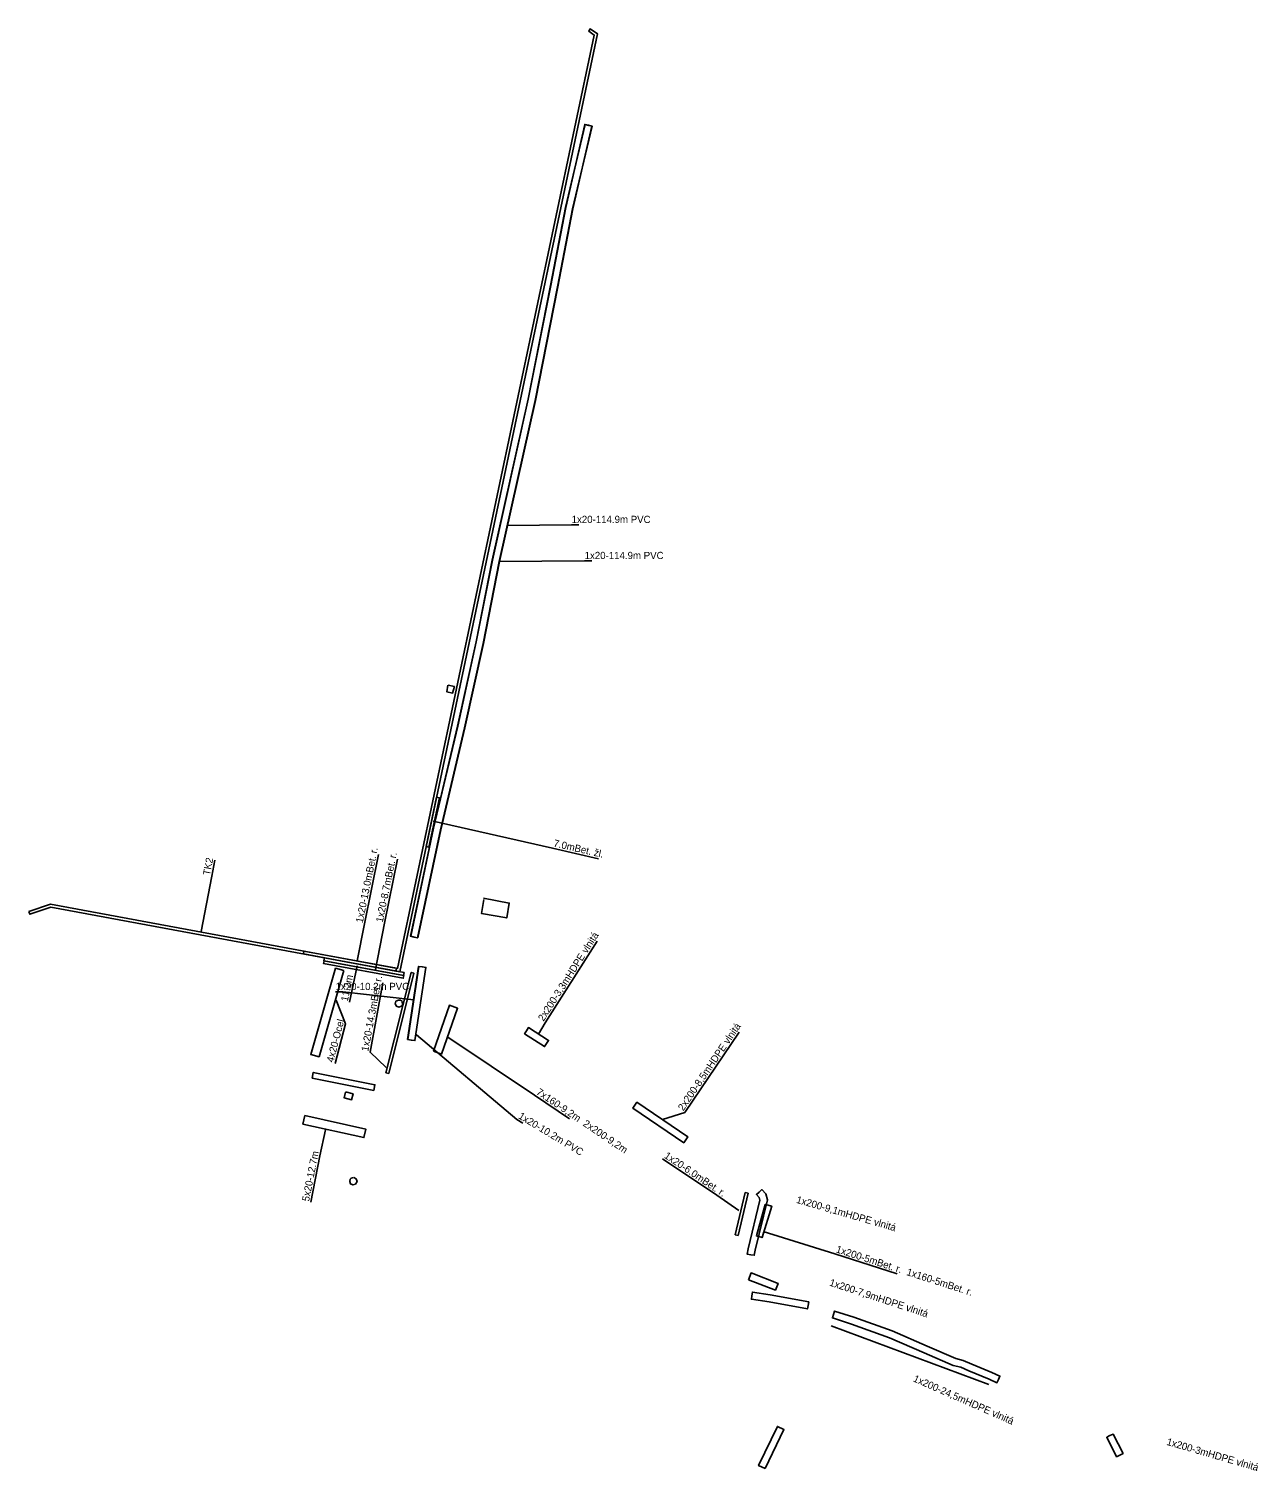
# Model space of a CAD drawing. Extents: x -739775 to -739098, y -1046233 to -1045777.
# Drawn here: x -739775.1 to -739605, y -1045977 to -1045777.5 of the extents above; entities that cross this region are included whole.
import ezdxf

# ---------------------------------------------------------------- set-up
doc = ezdxf.new("R2010")
doc.units = 0
for name, color, linetype in [('Chránička', 7, 'Continuous'), ('ST_CHRANICKA_POPIS', 7, 'Continuous'), ('ST_OBECNA_STAVBA', 7, 'Continuous')]:
    doc.layers.add(name, color=color, linetype=linetype)

msp = doc.modelspace()

# ---------------------------------------------------------------- linework, layer by layer
at = {"layer": 'Chránička'}
for points in [[(-739775.059, -1045899.583), (-739772.063, -1045898.585), (-739724.041, -1045907.446), (-739696.828, -1045778.31), (-739697.577, -1045777.78), (-739697.393, -1045777.45), (-739696.384, -1045778.138), (-739723.729, -1045907.91), (-739772.035, -1045898.997), (-739774.933, -1045899.962), (-739775.059, -1045899.583)], [(-739721.75, -1045903.11), (-739722.239, -1045903.007), (-739719.078, -1045888.051), (-739715.747, -1045873.949), (-739713.18, -1045862.278), (-739710.949, -1045850.957), (-739705.979, -1045828.687), (-739702.871, -1045812.944), (-739700.789, -1045802.165), (-739698.066, -1045790.695), (-739697.58, -1045790.81), (-739697.094, -1045790.925), (-739699.811, -1045802.375), (-739701.889, -1045813.136), (-739705.001, -1045828.893), (-739709.971, -1045851.163), (-739712.2, -1045862.482), (-739714.773, -1045874.171), (-739718.102, -1045888.269), (-739721.261, -1045903.213), (-739721.75, -1045903.11)], [(-739721.73, -1045903.11), (-739722.219, -1045903.006), (-739719.048, -1045888.051), (-739715.717, -1045873.949), (-739713.139, -1045862.278), (-739710.909, -1045850.957), (-739705.949, -1045828.687), (-739702.831, -1045812.944), (-739700.749, -1045802.167), (-739698.127, -1045790.679), (-739697.64, -1045790.79), (-739697.153, -1045790.901), (-739699.771, -1045802.373), (-739701.849, -1045813.136), (-739704.971, -1045828.893), (-739709.931, -1045851.163), (-739712.161, -1045862.482), (-739714.743, -1045874.171), (-739718.072, -1045888.269), (-739721.241, -1045903.214), (-739721.73, -1045903.11)], [(-739719.692, -1045890.686), (-739720.084, -1045890.604), (-739718.642, -1045883.754), (-739718.251, -1045883.836), (-739719.692, -1045890.686)], [(-739724.202, -1045907.416), (-739724.274, -1045907.81), (-739737.059, -1045905.451), (-739736.986, -1045905.058), (-739724.202, -1045907.416)], [(-739731.461, -1045907.757), (-739734.888, -1045919.671), (-739736.041, -1045919.34), (-739732.614, -1045907.426), (-739731.461, -1045907.757)], [(-739723.187, -1045908.415), (-739723.259, -1045908.809), (-739734.273, -1045906.777), (-739734.201, -1045906.384), (-739723.187, -1045908.415)], [(-739723.139, -1045908.019), (-739723.211, -1045908.413), (-739734.225, -1045906.38), (-739734.153, -1045905.987), (-739723.139, -1045908.019)], [(-739722.16, -1045917.36), (-739722.654, -1045917.285), (-739721.124, -1045907.165), (-739720.63, -1045907.24), (-739720.136, -1045907.315), (-739721.666, -1045917.435), (-739722.16, -1045917.36)], [(-739722.13, -1045917.36), (-739722.624, -1045917.286), (-739721.104, -1045907.166), (-739720.61, -1045907.24), (-739720.116, -1045907.314), (-739721.636, -1045917.434), (-739722.13, -1045917.36)], [(-739725.268, -1045921.976), (-739725.656, -1045921.878), (-739722.155, -1045908.013), (-739721.767, -1045908.111), (-739725.268, -1045921.976)], [(-739719.076, -1045918.909), (-739716.859, -1045912.557), (-739715.726, -1045912.953), (-739717.943, -1045919.305), (-739719.076, -1045918.909)], [(-739703.42, -1045917.84), (-739703.689, -1045918.261), (-739706.459, -1045916.491), (-739706.19, -1045916.07), (-739705.921, -1045915.649), (-739703.151, -1045917.419), (-739703.42, -1045917.84)], [(-739735.864, -1045922.627), (-739735.707, -1045921.843), (-739727.176, -1045923.55), (-739727.333, -1045924.334), (-739735.864, -1045922.627)], [(-739684.15, -1045931.17), (-739684.431, -1045931.584), (-739691.471, -1045926.804), (-739691.19, -1045926.39), (-739690.909, -1045925.976), (-739683.869, -1045930.756), (-739684.15, -1045931.17)], [(-739736.865, -1045927.815), (-739728.431, -1045929.689), (-739728.691, -1045930.86), (-739737.125, -1045928.986), (-739736.865, -1045927.815)], [(-739675.918, -1045938.461), (-739675.528, -1045938.553), (-739676.912, -1045944.391), (-739677.301, -1045944.299), (-739675.918, -1045938.461)], [(-739675.17, -1045947.06), (-739675.662, -1045946.97), (-739675.529, -1045946.246), (-739673.887, -1045939.511), (-739673.988, -1045939.16), (-739674.381, -1045938.725), (-739674.01, -1045938.39), (-739673.639, -1045938.055), (-739673.092, -1045938.66), (-739672.853, -1045939.489), (-739674.551, -1045946.454), (-739674.678, -1045947.15), (-739675.17, -1045947.06)], [(-739673.171, -1045940.135), (-739673.141, -1045940.135), (-739672.258, -1045940.366), (-739673.605, -1045944.699), (-739674.371, -1045944.472), (-739673.171, -1045940.135)], [(-739675.481, -1045950.52), (-739675.119, -1045949.588), (-739671.39, -1045951.036), (-739671.752, -1045951.968), (-739675.481, -1045950.52)], [(-739667.23, -1045954.08), (-739667.32, -1045954.572), (-739672.632, -1045953.603), (-739675.084, -1045953.234), (-739675.01, -1045952.74), (-739674.936, -1045952.246), (-739672.468, -1045952.617), (-739667.14, -1045953.588), (-739667.23, -1045954.08)], [(-739640.89, -1045964.32), (-739641.093, -1045964.777), (-739642.186, -1045964.29), (-739644.988, -1045963.149), (-739646.098, -1045962.643), (-739647.134, -1045962.374), (-739651.149, -1045960.619), (-739655.973, -1045958.546), (-739661.241, -1045956.673), (-739663.865, -1045955.815), (-739663.71, -1045955.34), (-739663.555, -1045954.865), (-739660.919, -1045955.727), (-739655.607, -1045957.614), (-739650.751, -1045959.701), (-739646.806, -1045961.426), (-739645.762, -1045961.697), (-739644.592, -1045962.231), (-739641.794, -1045963.37), (-739640.687, -1045963.863), (-739640.89, -1045964.32)], [(-739673.169, -1045976.667), (-739674.071, -1045976.233), (-739671.469, -1045970.826), (-739670.567, -1045971.26), (-739673.169, -1045976.667)], [(-739624.09, -1045974.79), (-739624.535, -1045975.018), (-739625.915, -1045972.328), (-739625.47, -1045972.1), (-739625.025, -1045971.872), (-739623.645, -1045974.562), (-739624.09, -1045974.79)]]:
    msp.add_lwpolyline(points, close=True, dxfattribs=at)
at = {"layer": 'ST_CHRANICKA_POPIS'}
for points in [[(-739708.82, -1045846.173), (-739699.953, -1045846.073), (-739698.953, -1045846.073)], [(-739709.971, -1045851.163), (-739698.155, -1045851.063), (-739697.155, -1045851.063)], [(-739719.107, -1045887.06), (-739702.584, -1045890.816), (-739696.23, -1045892.273)], [(-739751.225, -1045902.335), (-739749.76, -1045894.685), (-739749.324, -1045892.462)], [(-739729.619, -1045906.424), (-739728.613, -1045901.264), (-739726.686, -1045891.71)], [(-739727.104, -1045907.588), (-739725.843, -1045901.201), (-739724.042, -1045892.323)], [(-739704.536, -1045916.534), (-739703.628, -1045914.99), (-739696.399, -1045903.676)], [(-739730.684, -1045912.132), (-739730.012, -1045908.86), (-739729.618, -1045907.114)], [(-739725.621, -1045921.184), (-739727.844, -1045919.045), (-739726.061, -1045909.464)], [(-739732.616, -1045910.693), (-739731.616, -1045910.693), (-739721.802, -1045911.812)], [(-739732.683, -1045920.586), (-739731.262, -1045915.141), (-739732.521, -1045911.832)], [(-739721.432, -1045916.621), (-739707.55, -1045928.357), (-739706.694, -1045928.874)], [(-739717.103, -1045916.959), (-739705.078, -1045924.994), (-739700.244, -1045928.258)], [(-739687.389, -1045928.366), (-739684.291, -1045927.382), (-739676.751, -1045916.273)], [(-739736.048, -1045939.8), (-739734.782, -1045933.404), (-739734.027, -1045929.765)], [(-739687.375, -1045933.798), (-739679.854, -1045938.849), (-739676.795, -1045940.945)], [(-739673.445, -1045943.839), (-739663.531, -1045946.957), (-739654.908, -1045949.732)]]:
    msp.add_lwpolyline(points, dxfattribs=at)
at = {"layer": 'ST_OBECNA_STAVBA'}
msp.add_line((-739642.234, -1045965.045), (-739664.046, -1045956.918), dxfattribs=at)
for points in [[(-739717.043, -1045868.248), (-739716.173, -1045868.432), (-739716.431, -1045869.351), (-739717.237, -1045869.167), (-739717.076, -1045868.279)], [(-739712.093, -1045897.914), (-739712.432, -1045899.839), (-739708.922, -1045900.462), (-739708.582, -1045898.423), (-739712.149, -1045897.744)], [(-739723.685, -1045911.832), (-739723.459, -1045911.955), (-739723.394, -1045912.139), (-739723.362, -1045912.384), (-739723.394, -1045912.629), (-739723.878, -1045912.813), (-739724.201, -1045912.66), (-739724.362, -1045912.353), (-739724.265, -1045911.986), (-739723.91, -1045911.832), (-739723.588, -1045911.863)], [(-739731.231, -1045924.578), (-739731.424, -1045925.374), (-739730.392, -1045925.619), (-739730.199, -1045924.823), (-739731.231, -1045924.516)], [(-739730.097, -1045936.395), (-739729.759, -1045936.567), (-739729.646, -1045936.953), (-739729.872, -1045937.296), (-739730.21, -1045937.404), (-739730.572, -1045937.253), (-739730.662, -1045936.953), (-739730.617, -1045936.631), (-739730.436, -1045936.46), (-739730.143, -1045936.374)]]:
    msp.add_lwpolyline(points, dxfattribs=at)

# ---------------------------------------------------------------- texts
at = {"layer": 'ST_CHRANICKA_POPIS'}
for s, p in [('1x20-114.9m PVC', (-739699.953, -1045845.823)), ('1x20-114.9m PVC', (-739698.155, -1045850.813)), ('1x20-10.2m PVC', (-739732.616, -1045910.443))]:
    msp.add_text(s, height=1, dxfattribs=at).set_placement(p)
for s, rotation, p in [('7.0mBet. žl.', 347.07786, (-739702.528, -1045890.572)), ('1x20-13.0mBet. r.', 78.5942, (-739728.858, -1045901.214)), ('1x20-8.7mBet. r.', 78.52984, (-739726.088, -1045901.152)), ('TK2', 78.90354, (-739750.005, -1045894.636)), ('2x200-3,3mHDPE vlnitá', 57.42338, (-739703.839, -1045914.856)), ('11.2m', 78.39436, (-739730.929, -1045912.082)), ('1x20-14.3mBet. r.', 79.45637, (-739728.09, -1045918.999)), ('4x20-Ocel', 75.36673, (-739732.925, -1045920.523)), ('2x200-8,5mHDPE vlnitá', 55.83346, (-739684.498, -1045927.242)), ('7x160-9,2m  2x200-9,2m', 325.97266, (-739704.939, -1045924.786)), ('1x20-10.2m PVC', 328.87533, (-739707.421, -1045928.143)), ('5x20-12.7m', 78.80752, (-739736.293, -1045939.752)), ('1x20-6.0mBet. r.', 326.11577, (-739687.235, -1045933.591)), ('1x200-9,1mHDPE vlnitá', 343.91726, (-739668.94, -1045939.875)), ('1x200-5mBet. r.  1x160-5mBet. r.', 342.15758, (-739663.454, -1045946.719)), ('1x200-7,9mHDPE vlnitá', 341.91285, (-739664.37, -1045951.32)), ('1x200-24,5mHDPE vlnitá', 336.30576, (-739652.779, -1045964.564)), ('1x200-3mHDPE vlnitá', 343.87888, (-739617.699, -1045973.364))]:
    msp.add_text(s, height=1, rotation=rotation, dxfattribs=at).set_placement(p)

doc.saveas('drawing.dxf')
